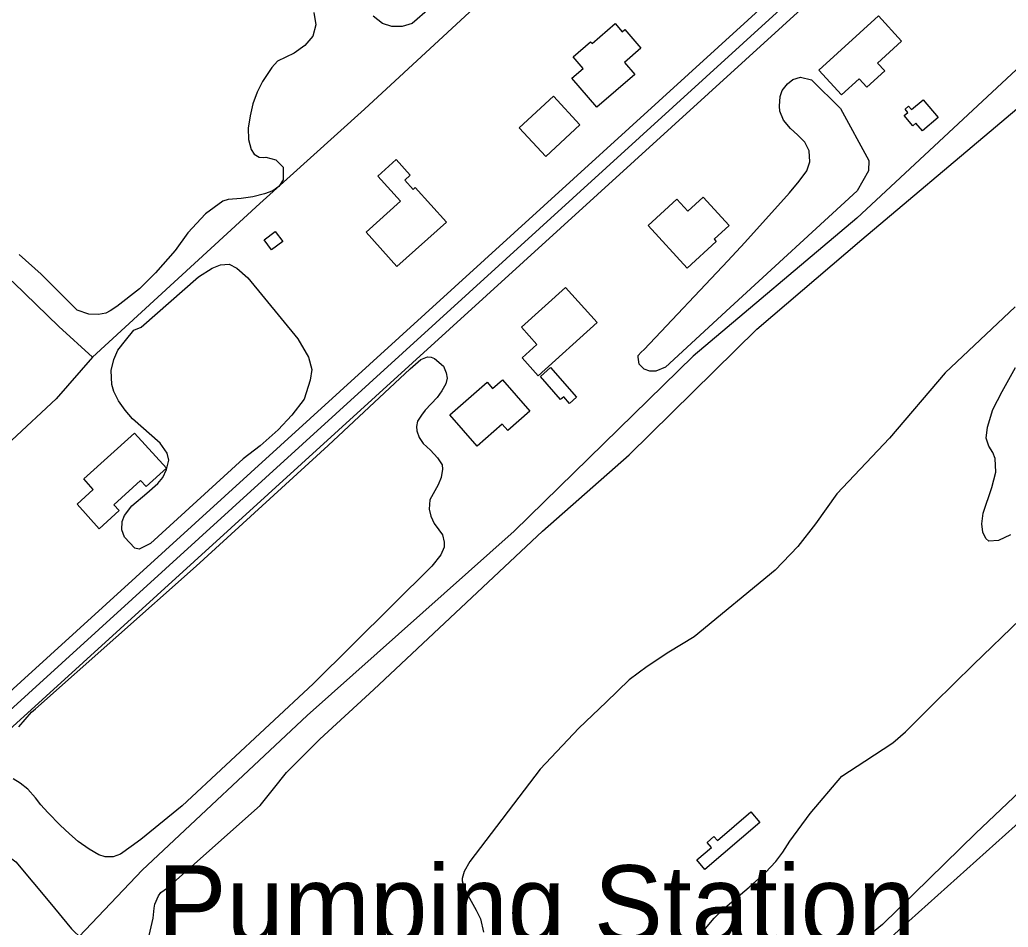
# Model space of a CAD drawing. Extents: x 3684037 to 3722149, y 433263 to 459021.
# Drawn here: x 3697074 to 3698136, y 452936 to 453911 of the extents above; entities that cross this region are included whole.
import ezdxf

# ---------------------------------------------------------------- set-up
doc = ezdxf.new("R2010")
doc.units = 0
for name, color, linetype in [('V-BLDG-OTLN', 7, 'Continuous'), ('V-RIVR-EDGE', 7, 'Continuous'), ('V-ROAD-CNTR', 7, 'Continuous'), ('V-SITE-VEGE', 7, 'Continuous'), ('V-STRM-IDEN', 7, 'Continuous'), ('V-TOPO-SHOR', 7, 'Continuous')]:
    doc.layers.add(name, color=color, linetype=linetype)

msp = doc.modelspace()

# ---------------------------------------------------------------- linework, layer by layer
at = {"layer": 'V-BLDG-OTLN'}
for points in [[(3697735, 453851.9), (3697694.2, 453816.8), (3697667.3, 453847.9), (3697679.5, 453858.4), (3697668.8, 453870.9), (3697687.4, 453887), (3697688.9, 453885.3), (3697713.7, 453906.7), (3697721.3, 453897.9), (3697724.1, 453900.3), (3697741.5, 453880.2), (3697723.8, 453864.9)], [(3697932.8, 453856.7), (3697996.7, 453915), (3698021.5, 453887.7), (3697995.7, 453864.2), (3698003.5, 453855.7), (3697984.3, 453838.2), (3697976, 453847.2), (3697957.1, 453830)], [(3697647.5, 453828.7), (3697676, 453797.9), (3697639.2, 453763.8), (3697610.7, 453794.5)], [(3698044.7, 453824.7), (3698061, 453805.6), (3698044.1, 453791.2), (3698036.9, 453799.6), (3698033.7, 453796.9), (3698024.5, 453807.7), (3698028.4, 453811), (3698025.4, 453814.5), (3698029, 453817.7), (3698032.2, 453814.1)], [(3697499, 453730.5), (3697532.4, 453693.3), (3697479.2, 453645.6), (3697446.1, 453682.6), (3697483.1, 453715.8), (3697458.9, 453742.8), (3697478.5, 453760.4), (3697493.6, 453743.6), (3697487.7, 453738.3), (3697496.6, 453728.4)], [(3697808.3, 453720.1), (3697836.2, 453689.6), (3697820.1, 453674.8), (3697822.3, 453672.4), (3697791.1, 453643.8), (3697749.1, 453689.6), (3697780.1, 453718), (3697791.9, 453705.1)], [(3697348.6, 453683.2), (3697356.6, 453672.6), (3697344.6, 453663.5), (3697336.6, 453674.1)], [(3697613.2, 453580.2), (3697660.5, 453623), (3697694.4, 453585.4), (3697631.2, 453528.2), (3697613.8, 453547.5), (3697629.7, 453561.8)], [(3697655.1, 453502.6), (3697633.4, 453527.4), (3697644.4, 453537), (3697672.3, 453505.1), (3697664.7, 453498.5), (3697658.5, 453505.5)], [(3697536.1, 453486.2), (3697576.2, 453521.2), (3697582.1, 453514.3), (3697592.9, 453523.7), (3697622.2, 453490.1), (3697598.3, 453469.2), (3697592.4, 453476), (3697565.4, 453452.5)], [(3697142.7, 453417.2), (3697197.2, 453466.6), (3697231.5, 453428.8), (3697209.8, 453409.1), (3697203.9, 453415.6), (3697175, 453389.4), (3697180.7, 453383.2), (3697159.3, 453363.8), (3697135.5, 453390.1), (3697152.9, 453405.9)], [(3697869.3, 453048.1), (3697810.3, 452997.6), (3697801.5, 453007.8), (3697817.3, 453021.3), (3697812.7, 453026.7), (3697819.9, 453032.9), (3697823.7, 453028.6), (3697859.7, 453059.4)]]:
    msp.add_lwpolyline(points, close=True, dxfattribs=at)
at = {"layer": 'V-RIVR-EDGE'}
msp.add_spline([(3696491, 456957), (3696499.5, 456945.3), (3696522.4, 456915.4), (3696551.1, 456881.7), (3696592.6, 456839.6), (3696607.9, 456824.6), (3696661.6, 456762.2), (3696696.3, 456732.6), (3696736.6, 456690.4), (3696783, 456647.4), (3696798.7, 456631.6), (3696862.9, 456574.8), (3696899.6, 456542.8), (3696931.1, 456518.5), (3696942.4, 456503.5), (3696952.4, 456495), (3696962.1, 456487.7), (3696987.2, 456470.6), (3697014.6, 456451.5), (3697061, 456420.3), (3697092.5, 456395.6), (3697134.1, 456360.7), (3697166.8, 456335.5), (3697185.7, 456316.5), (3697201.5, 456298.2), (3697211.5, 456284.5), (3697233.7, 456256.1), (3697255.9, 456231), (3697279.3, 456203.8), (3697316.4, 456164.9), (3697353.5, 456124), (3697376.9, 456099.7), (3697406.3, 456076.1), (3697430.1, 456057.9), (3697450.3, 456044.9), (3697520.1, 455982.4), (3697544.3, 455963.4), (3697581.9, 455942.3), (3697614.6, 455926), (3697632.8, 455913.8), (3697662.2, 455891.9), (3697710.3, 455848.1), (3697757.4, 455800.7), (3697792.1, 455767), (3697833.3, 455729.3), (3697868.4, 455696.9), (3697895.8, 455673.4), (3697933.7, 455633.7), (3697972.9, 455598.4), (3698039.5, 455539.6), (3698090.3, 455492.1), (3698135.9, 455447.6), (3698177, 455406.6), (3698217.7, 455359.2), (3698254.4, 455321.1), (3698281.5, 455292.7), (3698316.2, 455265.5), (3698357.4, 455240.8), (3698382, 455222.1), (3698407.8, 455195), (3698430.8, 455163.4), (3698450.9, 455141.9), (3698487.7, 455113.9), (3698517.5, 455091.2), (3698534.1, 455077), (3698556.2, 455049.4), (3698582.5, 455019.8), (3698614.7, 454987), (3698657.1, 454947.3), (3698691.4, 454913.6), (3698718, 454887.3), (3698807.2, 454806.6), (3698837.4, 454775.8), (3698881.4, 454739.7), (3698910.5, 454713.7), (3698949.2, 454677.6), (3698989.1, 454637.1), (3699039.1, 454591.7), (3699066.6, 454562.9), (3699088.8, 454545.5), (3699187.2, 454465.2), (3699228.4, 454429.9), (3699268.3, 454393.8), (3699300.6, 454360.6), (3699328.8, 454330.6), (3699382.5, 454285.1), (3699427.3, 454244.2), (3699474.5, 454199.6), (3699500.3, 454170.4), (3699532.6, 454139.2), (3699563.2, 454114.5), (3699588.7, 454093.8), (3699608.4, 454073.9), (3699636.7, 454041.5), (3699659.2, 454015.6), (3699675.8, 453998.5), (3699727, 453942.6), (3699768.9, 453898), (3699807.6, 453854.7), (3699829.4, 453837.6), (3699865.8, 453811.2), (3699885.1, 453793.8), (3699924.7, 453762.6), (3699939.6, 453754.8), (3699950.9, 453754.4), (3699975.6, 453746.7), (3700001.8, 453731.2), (3700023.6, 453714.2), (3700032.9, 453700.8), (3700036.1, 453688.7), (3700042.2, 453679.4), (3700052.6, 453667.2), (3700065.9, 453651), (3700072.4, 453638.5), (3700079.6, 453627.9), (3700095.3, 453607.3), (3700141.3, 453551.4), (3700161.5, 453521.4), (3700185.6, 453491.4), (3700219.9, 453452.9), (3700237.2, 453429.8), (3700255.4, 453407.5), (3700340.9, 453326.4), (3700393.4, 453280.6), (3700435.7, 453243.7), (3700480.9, 453207.6), (3700509.2, 453188.5), (3700535, 453172.3), (3700559.3, 453156.5), (3700600.4, 453130.9), (3700613.8, 453121.2), (3700623.5, 453116.3), (3700639.2, 453100.5), (3700647.7, 453090.7), (3700674.7, 453074.9), (3700691.3, 453060.7), (3700727.6, 453033.9), (3700758.2, 453008.8), (3700801.4, 452977.5), (3700837.4, 452952.4), (3700871.7, 452924.8), (3700904, 452898.4), (3700927.8, 452881), (3700958.4, 452857.9), (3701015.3, 452808), (3701048.4, 452780.4), (3701075.5, 452763), (3701104.9, 452743.5), (3701127.2, 452730.9), (3701156.6, 452713.4), (3701182.9, 452695.6), (3701204.7, 452682.2), (3701235.4, 452666.3), (3701255.6, 452654.1), (3701285.8, 452633), (3701312.9, 452607.1), (3701321.3, 452599.8), (3701332.2, 452591.7), (3701350.4, 452577.5), (3701370.6, 452560.4), (3701389.1, 452544.6), (3701408.9, 452532), (3701434.4, 452518.6), (3701456.2, 452512.1), (3701467.1, 452506.4), (3701486, 452491), (3701499.8, 452482.1), (3701518.7, 452468.3), (3701537.7, 452454.1), (3701554.3, 452439.5), (3701575.2, 452422.9), (3701592.2, 452410.3), (3701622.5, 452387.2), (3701647.1, 452368.5), (3701696.3, 452326.7), (3701727.8, 452300.4), (3701754, 452278.9), (3701780.7, 452258.2), (3701815.4, 452234.2), (3701863.8, 452194.9), (3701890.4, 452176.2), (3701916.7, 452162), (3701938.9, 452143.3), (3701962.3, 452129.9), (3701986.9, 452112.1), (3702012, 452090.6), (3702032.9, 452074.4), (3702051.1, 452058.6), (3702109.2, 452006.7), (3702158, 451973.4), (3702192.7, 451944.2), (3702212.1, 451923.9), (3702228.2, 451910.1), (3702239.6, 451906), (3702258.9, 451893.5), (3702276.7, 451876), (3702294.8, 451861.4), (3702325.5, 451839.1), (3702353.8, 451816.4), (3702388.5, 451789.6), (3702409.1, 451772.6), (3702442.6, 451743.4), (3702493.4, 451700.4), (3702516.8, 451677.7), (3702543.8, 451656.2), (3702589, 451624.5), (3702615.7, 451603.9), (3702648.4, 451577.9), (3702681.1, 451551.1), (3702714.1, 451522.3), (3702744.8, 451496.4), (3702761.8, 451479.4), (3702791.6, 451448.6), (3702806.5, 451427.9), (3702821.8, 451408), (3702843.2, 451386.6), (3702872.3, 451361), (3702910.6, 451327.8), (3702933.2, 451303), (3702957.8, 451275.5), (3702989.2, 451239), (3703050.2, 451184.3), (3703086, 451144.9), (3703114.7, 451113.3), (3703144.5, 451080.1), (3703160.6, 451061.9), (3703178, 451046.9), (3703202.6, 451019.7), (3703240.5, 450979.6), (3703264.7, 450956.5), (3703289.7, 450930.1), (3703316.7, 450902.2), (3703339.7, 450878.7), (3703374.4, 450840.2), (3703418.4, 450788.3), (3703459.1, 450738.8), (3703496.2, 450699.5), (3703592.6, 450595.8), (3703613.2, 450579.6), (3703630.9, 450558.9), (3703650.2, 450530.5), (3703671.6, 450496.5), (3703693.4, 450468.2), (3703725.2, 450432.9), (3703758.3, 450400.9), (3703788.6, 450373.7), (3703807.1, 450353), (3703820.4, 450338), (3703843, 450309.3), (3703868.4, 450275.6), (3703879.2, 450255.8), (3703887.7, 450233.5), (3703893.7, 450223.8), (3703916.3, 450193.4), (3703936, 450167.5), (3703951, 450147.7), (3704020.7, 450060.9), (3704036.8, 450041.5), (3704044.1, 450029.8), (3704061.8, 450007.9), (3704081.2, 449986.4), (3704102.9, 449954.4), (3704113.4, 449937.8), (3704138.4, 449903.4), (3704157.7, 449880.3), (3704175.5, 449851.9), (3704189.1, 449830), (3704204.9, 449813.4), (3704221.8, 449792.8), (3704273.8, 449711.8), (3704281.4, 449690.7), (3704297.1, 449666), (3704324.1, 449622.3), (3704340.6, 449601.6), (3704382.9, 449536), (3704402.7, 449506.8), (3704416, 449482.5), (3704431.7, 449459.4), (3704449.4, 449437.2), (3704472, 449410.4), (3704491.3, 449390.6), (3704521.2, 449354.9), (3704545.8, 449323.7), (3704553.8, 449308.3), (3704563.1, 449292.1), (3704576.8, 449271.1), (3704594.9, 449242.3), (3704618.7, 449204.2), (3704654.9, 449156), (3704685.2, 449111.9), (3704709.7, 449071.8), (3704733.9, 449034.1), (3704765.7, 448985.9), (3704789.9, 448945), (3704815.3, 448906.5), (3704829.3, 448881.4), (3704849.9, 448850.2), (3704868.8, 448820.7), (3704885, 448801.6), (3704901.1, 448781), (3704914, 448762.3), (3704925.6, 448740.1), (3704932.5, 448726.7), (3704949.8, 448698.4), (3704967.6, 448682.5), (3704988.1, 448670.8), (3705014.8, 448656.9), (3705046.3, 448639.9), (3705064.1, 448624.5), (3705092.3, 448592.1), (3705105.2, 448573.4), (3705120.5, 448554), (3705145.9, 448522.8), (3705180.2, 448483.9), (3705197.5, 448460.4), (3705228.5, 448416.2), (3705268.8, 448365.6), (3705295.8, 448328.3), (3705331.7, 448279.3), (3705359.5, 448238.8), (3705380, 448203.1), (3705402.2, 448152.5), (3705422.2, 448102), (3705439.5, 448066.3), (3705459.3, 448025.4)], degree=3, dxfattribs=at)
at = {"layer": 'V-ROAD-CNTR'}
for points in [[(3698386.5, 454393.3), (3697010.9, 453141.3)], [(3698396.6, 454382.2), (3697011.5, 453121.6)], [(3698406.7, 454371.1), (3697022.6, 453111.4)]]:
    msp.add_lwpolyline(points, dxfattribs=at)
at = {"layer": 'V-SITE-VEGE'}
for points in [[(3697390.1, 453918.6), (3697392.1, 453905.4), (3697388.8, 453893), (3697380.3, 453882.9), (3697368.7, 453874.9), (3697350.9, 453866.2), (3697345, 453859.5), (3697334.9, 453844.2), (3697329.2, 453832.9), (3697324.6, 453820.5), (3697321.5, 453807.6), (3697319.5, 453794.2), (3697319.7, 453782.1), (3697322.6, 453771.2), (3697325.9, 453766.3), (3697331.4, 453763.2), (3697335.7, 453762.7), (3697338.3, 453763.2), (3697349.2, 453760.1), (3697357.2, 453752.2), (3697356.9, 453738.7), (3697352.5, 453731.5), (3697346.1, 453726.9), (3697337.1, 453723.5), (3697324.4, 453720.4), (3697312, 453718.8), (3697297.9, 453717.5)], [(3697514.7, 453923), (3697495.8, 453906.8), (3697484.8, 453903.4), (3697473.9, 453903.4), (3697463.6, 453906.7), (3697453.8, 453914.7)], [(3697360.7, 453101.9), (3697396.6, 453137.7), (3697454.6, 453190.9), (3697635.7, 453361), (3697728.8, 453443.3), (3697865.9, 453578.2), (3697979, 453674.5), (3698122.4, 453795.6), (3698195.8, 453857.8)], [(3697297.9, 453717.5), (3697292.2, 453715.7), (3697273.4, 453702.3), (3697254.5, 453681.7), (3697240.9, 453662.8), (3697220, 453638.8), (3697202.5, 453621.5), (3697178.2, 453602.7), (3697171, 453598), (3697166.6, 453595.5), (3697158.6, 453593.9), (3697148.3, 453594.4), (3697135.5, 453598.7)], [(3697135.5, 453598.7), (3697096.9, 453637.2), (3697073.4, 453658.5)], [(3698143.6, 453602.1), (3698068.4, 453531.2), (3698008.6, 453461), (3697951.9, 453401.1), (3697929.2, 453368.9), (3697910.1, 453344.6), (3697885.7, 453319.3), (3697798.8, 453247.6), (3697771.5, 453231.1), (3697748.3, 453215.8), (3697728.9, 453201.4), (3697704.2, 453177.4), (3697674.8, 453149.5), (3697633.3, 453105.4), (3697557.6, 453006), (3697551.4, 452995.5), (3697549.3, 452987.7), (3697549.3, 452985.2), (3697551.1, 452978.5), (3697557.1, 452966.8), (3697564.6, 452954), (3697569.2, 452944.4), (3697572.3, 452930.2)], [(3697072.9, 453150.9), (3697086.6, 453166.7), (3697091, 453170.1), (3697263.4, 453323.6), (3697405.4, 453453.1), (3697493.4, 453535.5), (3697505, 453545.6), (3697512, 453548.4), (3697516.1, 453548.2), (3697519.8, 453546.6), (3697529.3, 453538.4), (3697532.2, 453531.4), (3697533.2, 453525.5), (3697531.7, 453519.5), (3697527.5, 453512), (3697522.6, 453504.8), (3697509.7, 453491.1), (3697505.6, 453485.9), (3697501.5, 453479.2), (3697500.2, 453473.5), (3697500.7, 453469.1), (3697503, 453461.7), (3697507.4, 453455.2), (3697515.2, 453448.2), (3697522.9, 453440), (3697527.8, 453432.5), (3697528.1, 453427.6), (3697526.8, 453418.8), (3697523.5, 453411), (3697514.7, 453394.8), (3697513.9, 453384.7), (3697515.7, 453377.2), (3697519.4, 453369.2), (3697524.3, 453362.7), (3697528.2, 453357.1), (3697530, 453349.3), (3697530, 453343.9), (3697526.6, 453335.6), (3697516.8, 453323.5), (3697389.3, 453197.1), (3697248.4, 453066.1), (3697204, 453029.9), (3697193.6, 453022.1), (3697182.3, 453013.9), (3697174.5, 453011), (3697165.8, 453011.3), (3697159, 453013.3), (3697148.4, 453019.3), (3697136.8, 453027.5), (3697127.3, 453036), (3697117.4, 453045.3), (3697104, 453058.7), (3697096.5, 453067), (3697090.8, 453074.5), (3697082.8, 453084), (3697074.5, 453090.5), (3697067, 453094.9)], [(3698138.6, 453357.2), (3698125.7, 453351.2), (3698115.4, 453350.4), (3698112.1, 453353.3), (3698108.7, 453360.2), (3698107.9, 453369), (3698109.2, 453380.3), (3698118.7, 453407.9), (3698122.9, 453424.7), (3698122.3, 453439.4), (3698119.7, 453445.6), (3698115.4, 453452.3), (3698112.3, 453461.1), (3698113.8, 453472.9), (3698119.5, 453491.8), (3698129.5, 453511.1), (3698143.9, 453536.9)], [(3697800, 452921.1), (3697820.1, 452945.1), (3697829.4, 452954.6), (3697857.8, 452978.6), (3697875.3, 452994.4), (3697886.6, 453006), (3697894.1, 453016.3), (3697901.6, 453027.9), (3697923.5, 453057.6), (3697957.2, 453097.9), (3697982, 453113.9), (3698012.1, 453133.5), (3698025.8, 453145.6), (3698035.9, 453155.4), (3698056.7, 453176.3), (3698098.7, 453217.9), (3698149.5, 453266.6)], [(3697213.1, 452926.7), (3697217.4, 452945.2), (3697218.5, 452956.1), (3697219.2, 452960.2), (3697223.1, 452969.2), (3697225.7, 452972.8), (3697232.6, 452977.7), (3697332.4, 453066.5), (3697346.8, 453084.1), (3697360.7, 453101.9)], [(3698155.6, 453087.7), (3698101.4, 453036.6), (3698001.2, 452938.5), (3697925.7, 452876.8)]]:
    msp.add_lwpolyline(points, dxfattribs=at)
for points in [[(3697745, 453556.2), (3697834.8, 453651.8), (3697853.1, 453671.5), (3697901.3, 453724.6), (3697911.6, 453737.3), (3697919.9, 453748.2), (3697923, 453758), (3697922.2, 453769.7), (3697917.5, 453779.2), (3697909.8, 453787), (3697902.2, 453793.7), (3697894.7, 453802.8), (3697890.8, 453812.4), (3697890.3, 453817.8), (3697891.1, 453828.2), (3697893.4, 453834.6), (3697898.9, 453841.9), (3697904.8, 453846.5), (3697913.1, 453849.1), (3697924.7, 453846.3), (3697955.8, 453815.3), (3697986.2, 453759.6), (3697985.9, 453748.5), (3697973.7, 453727), (3697837.4, 453601.6), (3697768, 453537.3), (3697757.4, 453532.9), (3697751, 453532.9), (3697745, 453535.3), (3697739.6, 453540.7), (3697738.5, 453548.2), (3697738.5, 453550), (3697741.9, 453553.6)], [(3697204.6, 453580.3), (3697266, 453634.3), (3697280.7, 453643.6), (3697289.7, 453647.5), (3697299, 453648), (3697307.3, 453643.9), (3697319.2, 453633.3), (3697372.7, 453568), (3697384.3, 453548.2), (3697387.7, 453535), (3697385.9, 453523.4), (3697379.7, 453503), (3697366.5, 453485.9), (3697351.6, 453469.9), (3697332.2, 453452.8), (3697314.1, 453438.9), (3697214.3, 453347.9), (3697202.4, 453341.7), (3697197.7, 453343), (3697186.4, 453354.6), (3697183.5, 453362.6), (3697184, 453371.4), (3697186.6, 453377.8), (3697194.4, 453388.2), (3697210.6, 453401.9), (3697222.5, 453412.2), (3697227.9, 453418.7), (3697231.8, 453427.4), (3697234.3, 453437.5), (3697232.5, 453444.8), (3697224.8, 453455.6), (3697195.3, 453481.7), (3697187.1, 453491.2), (3697180.1, 453501.3), (3697174.9, 453511.3), (3697173.1, 453518.8), (3697172.3, 453533.8), (3697174.9, 453545.7), (3697179.5, 453555.5), (3697187.5, 453566.1), (3697196.6, 453577)]]:
    msp.add_lwpolyline(points, close=True, dxfattribs=at)
at = {"layer": 'V-TOPO-SHOR'}
msp.add_line((3697115.8, 453581.1), (3697152.3, 453548.1), dxfattribs=at)
for points in [[(3698532.9, 454209.7), (3698385.6, 454074.9), (3698160.3, 453871.6), (3697973.6, 453697.4), (3697797.7, 453549.3), (3697605.1, 453361.1), (3697382.8, 453163.2), (3697205.7, 452997), (3697138, 452925.6)], [(3697716.1, 454057.9), (3697576, 453936.4), (3697444.6, 453814.7), (3697332, 453713.4)], [(3696694.6, 453960.2), (3696712.3, 453952.9), (3696734, 453937.9), (3696761.5, 453911.1), (3696787.2, 453886.7), (3696829.2, 453846.3), (3696882.3, 453801.3), (3696922, 453761.8), (3696987.7, 453699.9), (3697032.2, 453659), (3697067.4, 453628.5), (3697115.8, 453581.1)], [(3697332, 453713.4), (3697152.3, 453548.1), (3697113.1, 453503.3)], [(3698762.3, 453610.8), (3698587, 453453.9), (3698370, 453250.1), (3698216.2, 453109.6), (3698018.8, 452932.6), (3697871.8, 452795.2), (3697690.6, 452628.8), (3697549.2, 452495.8), (3697433.1, 452389.1), (3697377.6, 452340.6)], [(3697113.1, 453503.3), (3697065.6, 453458.8), (3697013.7, 453415.1), (3696955.9, 453361.9), (3696907.9, 453317.8), (3696865.4, 453284.5)], [(3697133.4, 452862.4), (3697127.9, 452879.8), (3697121.4, 452890.2), (3697106.7, 452901), (3697093.3, 452902), (3697068.3, 452899.3), (3697036.8, 452900.6), (3697011.5, 452921.2), (3697006.7, 452931), (3697009.7, 452965.9), (3697011.6, 452993.3), (3697007.5, 453000.2), (3696995, 453014.6), (3696990.3, 453023.3), (3696988.9, 453035.5), (3696994.6, 453041.4), (3697003.9, 453047.3), (3697012.6, 453047.4), (3697037.9, 453029.2), (3697069.6, 453005.8), (3697106.4, 452962.1), (3697129.5, 452933.9), (3697140.7, 452923)]]:
    msp.add_lwpolyline(points, dxfattribs=at)

# ---------------------------------------------------------------- texts
at = {"layer": 'V-STRM-IDEN'}
msp.add_text('Pumping Station', height=83, dxfattribs=at).set_placement((3697222.1, 452919.1))

doc.saveas('drawing.dxf')
